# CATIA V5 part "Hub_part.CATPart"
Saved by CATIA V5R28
Part number: Hub_part
Definition: design
Nomenclature: Hub_part
Source: Unknown
Bounding box of the stored display mesh (mm): x -10.05 to 10.05, y -10.03 to 10.03, z -1.287 to 13.901
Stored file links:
  D:\paraturbo-cad\STEP\Turbocompressor_for_Christophe\Hub_part.CATPart
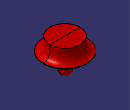
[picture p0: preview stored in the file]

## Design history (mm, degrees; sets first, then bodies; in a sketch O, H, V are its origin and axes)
Body1 "MANIFOLD_SOLID_BREP #27571" (main body)
  Solid1: solid without history
Body2 "MANIFOLD_SOLID_BREP #29197"
  Solid2: solid without history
